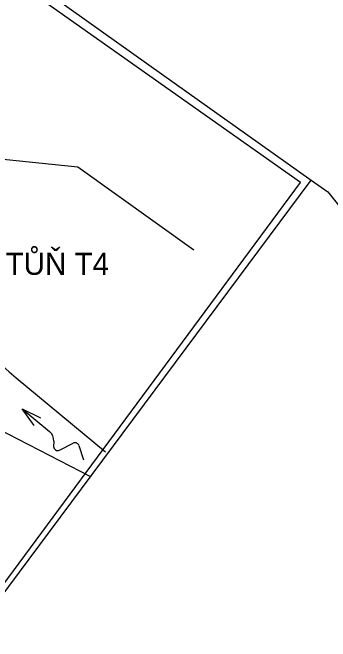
# Model space of a CAD drawing. Extents: x -564037 to -563722, y -1163561 to -1163412.
# Drawn here: x -563845.58 to -563827.59, y -1163519.34 to -1163483.71 of the extents above; entities that cross this region are included whole.
import ezdxf

# ---------------------------------------------------------------- set-up
doc = ezdxf.new("R2010")
doc.units = 0
for name, color, linetype in [('4', 7, 'Continuous'), ('5', 7, 'Continuous'), ('Hranice parcel', 7, 'Continuous'), ('Obvod PU', 7, 'Continuous'), ('podélný profil', 7, 'Continuous')]:
    doc.layers.add(name, color=color, linetype=linetype)

msp = doc.modelspace()

# ---------------------------------------------------------------- linework, layer by layer
for points in [[(-563982.839, -1163488.47), (-563983.409, -1163491.846), (-563990.891, -1163500.051), (-563993.495, -1163501.54), (-564001.695, -1163505.76), (-564021.072, -1163514.028), (-564021.939, -1163519.359), (-564028.021, -1163535.92), (-563982.332, -1163543.556), (-563870.708, -1163549.442), (-563829.278, -1163493.346), (-563857.264, -1163473.56), (-563873.956, -1163464.96), (-563885.354, -1163462.845), (-563964.187, -1163417.135), (-563977.612, -1163460.096), (-563977.509, -1163470.055), (-563981.031, -1163479.642), (-563982.839, -1163488.47)], [(-563835.323, -1163497.175), (-563841.877, -1163492.459), (-563849.248, -1163491.704)]]:
    msp.add_lwpolyline(points)
at = {"layer": '5'}
for p, q in [((-563871.424, -1163494.398), (-563841.172, -1163509.993)), ((-563845.378, -1163504.4), (-563840.311, -1163508.591))]:
    msp.add_line(p, q, dxfattribs=at)
msp.add_arc((-563829.443, -1163485.136), 25, 211.1947, 230.4029, dxfattribs=at)
at = {"layer": 'Hranice parcel'}
msp.add_lwpolyline([(-564028.91, -1163536.42), (-563982.72, -1163544.1), (-563870.61, -1163549.59), (-563828.67, -1163493.21)], dxfattribs=at)
at = {"layer": 'Obvod PU'}
for p, q in [((-563847.48, -1163479.82), (-563837.86, -1163486.67)), ((-563837.86, -1163486.67), (-563828.67, -1163493.21))]:
    msp.add_line(p, q, dxfattribs=at)
msp.add_lwpolyline([(-563828.67, -1163493.21), (-563827.74, -1163493.87), (-563826.505, -1163495.405)], dxfattribs=at)
at = {"layer": 'podélný profil'}
for points in [[(-563844.352, -1163507.099), (-563845.039, -1163506.16), (-563843.991, -1163506.665)], [(-563845.039, -1163506.16), (-563843.489, -1163507.451)], [(-563843.245, -1163507.989), (-563843.253, -1163508.296)], [(-563842.925, -1163508.503), (-563842.15, -1163508.107)], [(-563841.833, -1163508.239), (-563841.571, -1163509.049)]]:
    msp.add_lwpolyline(points, dxfattribs=at)
for centre, radius, start, end in [((-563843.922, -1163507.971), 0.677, 358.5156, 50.2101), ((-563843.028, -1163508.302), 0.226, 178.5177, 297.0647), ((-563842.047, -1163508.308), 0.226, 17.9212, 117.0384)]:
    msp.add_arc(centre, radius, start, end, dxfattribs=at)

# ---------------------------------------------------------------- texts
at = {"layer": '4'}
msp.add_text('TŮŇ T4', height=1.25, rotation=360, dxfattribs=at).set_placement((-563845.97, -1163498.57))

doc.saveas('drawing.dxf')
